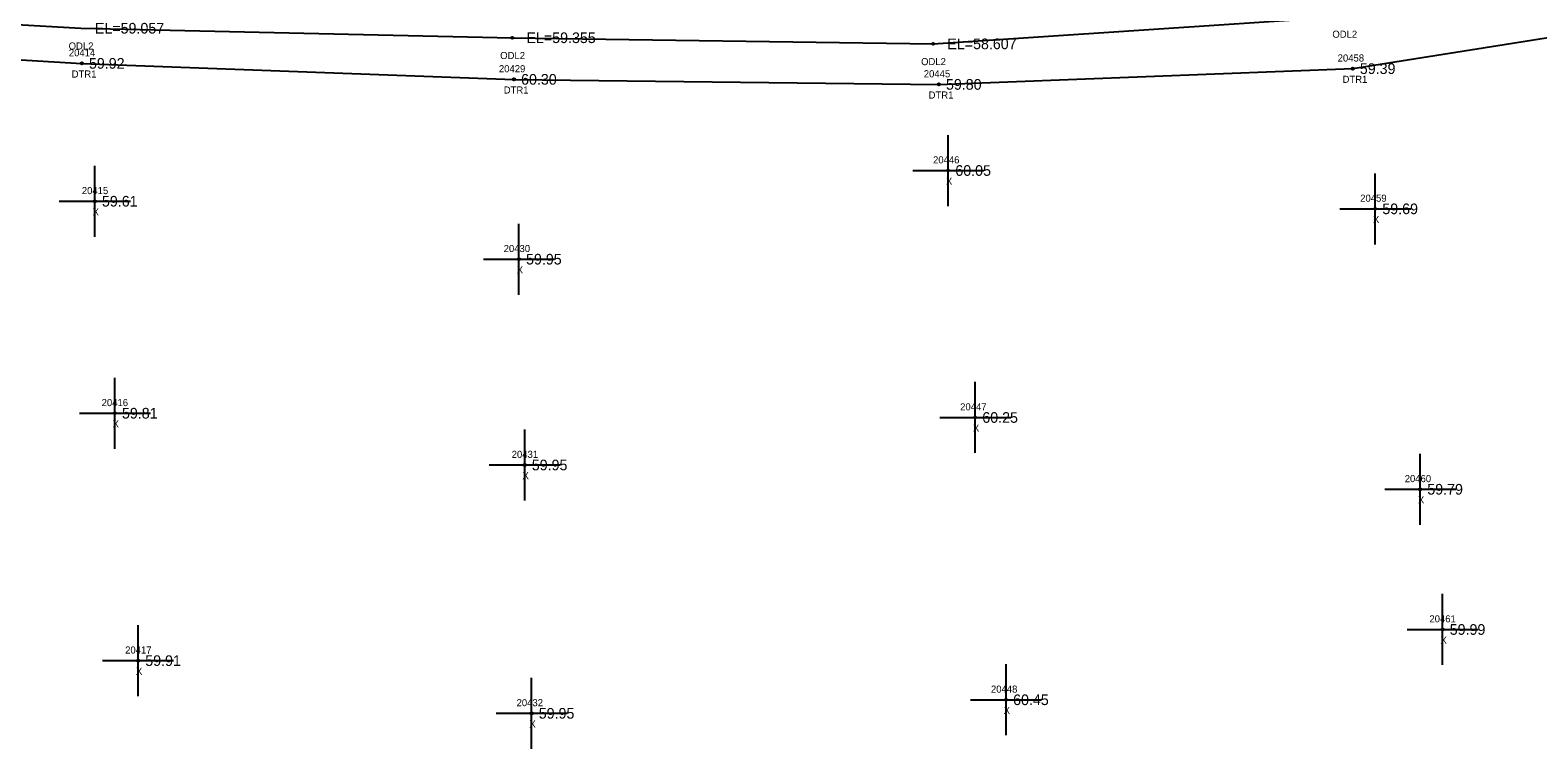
# Model space of a CAD drawing. Extents: x 2420351 to 2422725, y 845330 to 846558.
# Drawn here: x 2421166.9 to 2421379.3, y 845560.1 to 845661.3 of the extents above; entities that cross this region are included whole.
import ezdxf

# ---------------------------------------------------------------- set-up
doc = ezdxf.new("R2010")
doc.units = 0
for name, color, linetype in [('RD_EX_H2O', 7, 'Continuous'), ('RD_EX_H2O_txCode', 7, 'Continuous'), ('RD_EX_Misc', 7, 'Continuous'), ('RD_EX_Misc_txCode', 7, 'Continuous'), ('RD_EX_TX_H2O_ELEV', 7, 'Continuous'), ('RD_EX_TX_Misc_ELEV', 7, 'Continuous'), ('RD_SMD_Locator', 7, 'Continuous')]:
    doc.layers.add(name, color=color, linetype=linetype)

msp = doc.modelspace()

# ---------------------------------------------------------------- linework, layer by layer
at = {"layer": 'RD_EX_H2O'}
for points in [[(2420680.88, 845704.69), (2420749.16, 845701.08), (2420794.33, 845696.81), (2420899.79, 845687.85), (2421017.53, 845674.81), (2421112.48, 845665.13), (2421174.04, 845661.58), (2421234.82, 845660.24), (2421294.09, 845659.38), (2421352.01, 845663.24), (2421417.66, 845672.42), (2421424.72, 845673.17)], [(2420681.1, 845702.44), (2420748.92, 845698.41), (2420794.23, 845693.69), (2420899.45, 845684.25), (2421017.43, 845671.31), (2421111.87, 845660.39), (2421174.2, 845656.63), (2421235.06, 845654.38), (2421294.9, 845653.67), (2421353.19, 845655.89), (2421424.22, 845667.22)]]:
    msp.add_lwpolyline(points, dxfattribs=at)
at = {"layer": 'RD_EX_Misc'}
for p, q in [((2421296.22, 845636.54), (2421296.22, 845646.54)), ((2421176.03, 845632.21), (2421176.03, 845642.21)), ((2421291.22, 845641.54), (2421301.22, 845641.54)), ((2421356.36, 845631.14), (2421356.36, 845641.14)), ((2421171.03, 845637.21), (2421181.03, 845637.21)), ((2421351.36, 845636.14), (2421361.36, 845636.14)), ((2421235.76, 845624.05), (2421235.76, 845634.05)), ((2421230.76, 845629.05), (2421240.76, 845629.05)), ((2421178.85, 845602.35), (2421178.85, 845612.35)), ((2421300.02, 845601.75), (2421300.02, 845611.75)), ((2421173.85, 845607.35), (2421183.85, 845607.35)), ((2421295.02, 845606.75), (2421305.02, 845606.75)), ((2421236.57, 845595.06), (2421236.57, 845605.06)), ((2421362.69, 845591.64), (2421362.69, 845601.64)), ((2421231.57, 845600.06), (2421241.57, 845600.06)), ((2421357.69, 845596.64), (2421367.69, 845596.64)), ((2421365.85, 845571.89), (2421365.85, 845581.89)), ((2421182.13, 845567.5), (2421182.13, 845577.5)), ((2421360.85, 845576.89), (2421370.85, 845576.89)), ((2421177.13, 845572.5), (2421187.13, 845572.5)), ((2421304.36, 845561.99), (2421304.36, 845571.99)), ((2421237.55, 845560.08), (2421237.55, 845570.08)), ((2421299.36, 845566.99), (2421309.36, 845566.99)), ((2421232.55, 845565.08), (2421242.55, 845565.08))]:
    msp.add_line(p, q, dxfattribs=at)
at = {"layer": 'RD_SMD_Locator'}
for centre in [(2421234.82, 845660.24), (2421294.09, 845659.38), (2421174.2, 845656.63), (2421353.19, 845655.89), (2421235.06, 845654.38), (2421294.9, 845653.67), (2421296.22, 845641.54), (2421176.03, 845637.21), (2421356.36, 845636.14), (2421235.76, 845629.05), (2421178.85, 845607.35), (2421300.02, 845606.75), (2421236.57, 845600.06), (2421362.69, 845596.64), (2421365.85, 845576.89), (2421182.13, 845572.5), (2421304.36, 845566.99), (2421237.55, 845565.08)]:
    msp.add_circle(centre, 0.15, dxfattribs=at)

# ---------------------------------------------------------------- texts
at = {"layer": 'RD_EX_H2O_txCode'}
for s, p in [('ODL2', (2421350.32, 845660.24)), ('ODL2', (2421172.34, 845658.58)), ('20414', (2421172.37, 845657.63)), ('ODL2', (2421233.12, 845657.24)), ('20458', (2421351.07, 845656.89)), ('DTR1', (2421172.77, 845654.63)), ('20429', (2421232.94, 845655.38)), ('ODL2', (2421292.4, 845656.38)), ('20445', (2421292.78, 845654.67)), ('DTR1', (2421351.76, 845653.89)), ('DTR1', (2421233.62, 845652.38)), ('DTR1', (2421293.46, 845651.67))]:
    msp.add_text(s, height=1, dxfattribs=at).set_placement(p)
at = {"layer": 'RD_EX_Misc_txCode'}
for s, p in [('20446', (2421294.08, 845642.54)), ('20415', (2421174.2, 845638.21)), ('X', (2421295.9, 845639.54)), ('20459', (2421354.24, 845637.14)), ('X', (2421175.72, 845635.21)), ('X', (2421356.04, 845634.14)), ('20430', (2421233.61, 845630.05)), ('X', (2421235.45, 845627.05)), ('20416', (2421176.99, 845608.35)), ('20447', (2421297.9, 845607.75)), ('X', (2421178.53, 845605.35)), ('X', (2421299.7, 845604.75)), ('20431', (2421234.74, 845601.06)), ('X', (2421236.26, 845598.06)), ('20460', (2421360.51, 845597.64)), ('X', (2421362.37, 845594.64)), ('20461', (2421363.99, 845577.89)), ('X', (2421365.54, 845574.89)), ('20417', (2421180.3, 845573.5)), ('X', (2421181.82, 845570.5)), ('20448', (2421302.24, 845567.99)), ('20432', (2421235.43, 845566.08)), ('X', (2421304.04, 845564.99)), ('X', (2421237.23, 845563.08))]:
    msp.add_text(s, height=1, dxfattribs=at).set_placement(p)
at = {"layer": 'RD_EX_TX_H2O_ELEV'}
for s, p in [('EL=59.057', (2421176.04, 845660.83)), ('EL=59.355', (2421236.82, 845659.49)), ('EL=58.607', (2421296.09, 845658.63)), ('59.92', (2421175.2, 845655.88)), ('59.39', (2421354.19, 845655.14)), ('60.30', (2421236.06, 845653.63)), ('59.80', (2421295.9, 845652.92))]:
    msp.add_text(s, height=1.5, dxfattribs=at).set_placement(p)
at = {"layer": 'RD_EX_TX_Misc_ELEV'}
for s, p in [('60.05', (2421297.22, 845640.79)), ('59.61', (2421177.03, 845636.46)), ('59.69', (2421357.36, 845635.39)), ('59.95', (2421236.76, 845628.3)), ('59.81', (2421179.85, 845606.6)), ('60.25', (2421301.02, 845606)), ('59.95', (2421237.57, 845599.31)), ('59.79', (2421363.69, 845595.89)), ('59.99', (2421366.85, 845576.14)), ('59.91', (2421183.13, 845571.75)), ('60.45', (2421305.36, 845566.24)), ('59.95', (2421238.55, 845564.33))]:
    msp.add_text(s, height=1.5, dxfattribs=at).set_placement(p)

doc.saveas('drawing.dxf')
